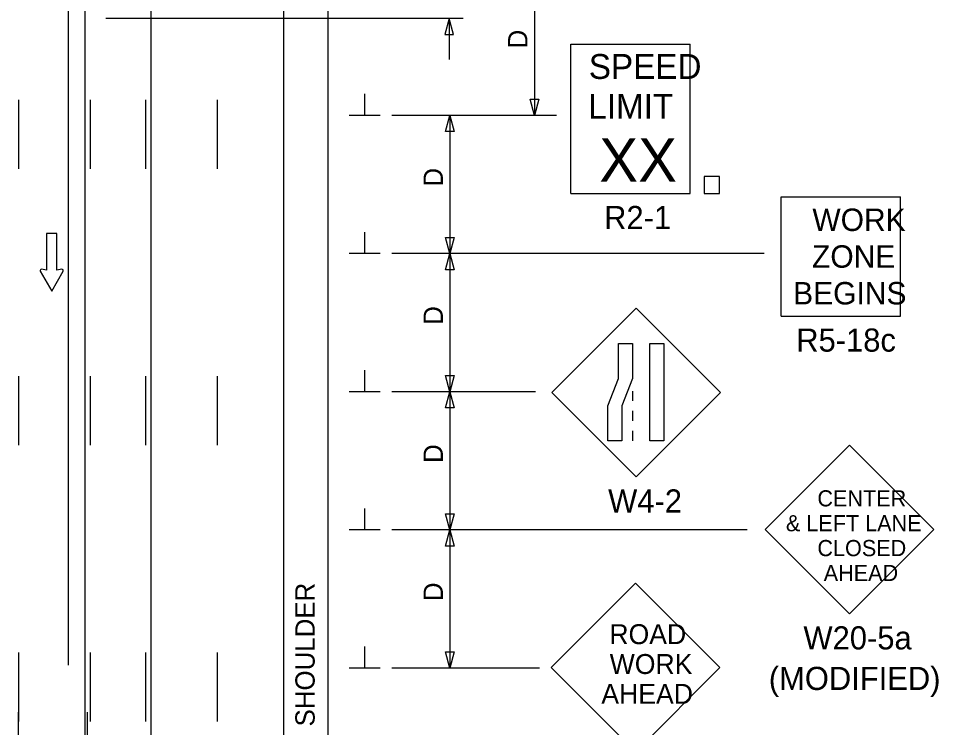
# Model space of a CAD drawing. Extents: x 16735 to 18475, y 6983 to 8262.
# Drawn here: x 17017.1 to 17350.3, y 7410.5 to 7667.2 of the extents above; entities that cross this region are included whole.
import ezdxf

# ---------------------------------------------------------------- set-up
doc = ezdxf.new("R2010")
doc.units = 0
for name, color, linetype in [('ALI_LEGAL_EX', 7, 'Continuous'), ('MT_SCRATCH_LEVEL_E', 7, 'Continuous'), ('PAVT_EDGE_EX', 7, 'Continuous'), ('TRAFFIC_SIGNS_PR', 7, 'Continuous'), ('TYPICAL_TEXT_DIMEN_PR', 7, 'Continuous')]:
    doc.layers.add(name, color=color, linetype=linetype)

msp = doc.modelspace()

# ---------------------------------------------------------------- linework, layer by layer
at = {"layer": 'ALI_LEGAL_EX'}
for points in [[(17017.08, 7637.7), (17017.08, 7612.7)], [(17043.08, 7637.7), (17043.08, 7612.7)], [(17063.08, 7637.7), (17063.08, 7612.7)], [(17089.08, 7637.7), (17089.08, 7612.7)], [(17017.08, 7537.7), (17017.08, 7512.7)], [(17043.08, 7537.7), (17043.08, 7512.7)], [(17063.08, 7537.7), (17063.08, 7512.7)], [(17089.08, 7537.7), (17089.08, 7512.7)], [(17017.08, 7437.7), (17017.08, 7412.7)], [(17043.08, 7437.7), (17043.08, 7412.7)], [(17063.08, 7437.7), (17063.08, 7412.7)], [(17089.08, 7437.7), (17089.08, 7412.7)]]:
    msp.add_lwpolyline(points, dxfattribs=at)
at = {"layer": 'MT_SCRATCH_LEVEL_E'}
for p, q in [((17031.01, 7589.33), (17027.26, 7589.33)), ((17027.26, 7589.33), (17027.26, 7576.07)), ((17031.01, 7589.33), (17027.26, 7589.33)), ((17027.26, 7589.33), (17027.26, 7576.07)), ((17031.01, 7576.07), (17031.01, 7589.33)), ((17031.01, 7576.07), (17031.01, 7589.33)), ((17025.01, 7575.7), (17029.15, 7568.46)), ((17025.01, 7575.7), (17029.15, 7568.46)), ((17027.26, 7576.07), (17025.49, 7576.38)), ((17027.26, 7576.07), (17025.49, 7576.38)), ((17029.15, 7568.46), (17033.27, 7575.7)), ((17029.15, 7568.46), (17033.27, 7575.7)), ((17032.78, 7576.38), (17031.01, 7576.07)), ((17032.78, 7576.38), (17031.01, 7576.07))]:
    msp.add_line(p, q, dxfattribs=at)
for centre, start, end in [((17025.42, 7575.92), 80.0362, 209.7731), ((17025.42, 7575.92), 80.0362, 209.7731), ((17032.86, 7575.92), 330.4248, 99.9638), ((17032.86, 7575.92), 330.4248, 99.9638)]:
    msp.add_arc(centre, 0.463, start, end, dxfattribs=at)
at = {"layer": 'PAVT_EDGE_EX'}
for p, q in [((17035.15, 8262.34), (17035.15, 7433.15)), ((17041.08, 8195.21), (17041.08, 7357.91)), ((17065.08, 8195.21), (17065.08, 7357.91)), ((17113.08, 8195.21), (17113.08, 7357.91)), ((17129.08, 8195.21), (17129.08, 7357.91))]:
    msp.add_line(p, q, dxfattribs=at)
for points in [[(17017.08, 7391.16), (17017.08, 7416.16)], [(17042.08, 7391.16), (17042.08, 7416.16)]]:
    msp.add_lwpolyline(points, dxfattribs=at)
at = {"layer": 'TRAFFIC_SIGNS_PR'}
for p, q in [((17217.14, 7657.79), (17260.34, 7657.79)), ((17217.14, 7603.79), (17217.14, 7657.79)), ((17260.34, 7603.79), (17260.34, 7657.79)), ((17217.14, 7603.79), (17260.34, 7603.79)), ((17293.32, 7559.44), (17293.32, 7602.64)), ((17293.32, 7602.64), (17336.52, 7602.64)), ((17336.52, 7559.44), (17336.52, 7602.64)), ((17240.78, 7562.32), (17210.24, 7531.78)), ((17271.33, 7531.78), (17240.78, 7562.32)), ((17293.32, 7559.44), (17336.52, 7559.44)), ((17210.24, 7531.78), (17240.78, 7501.23)), ((17239.38, 7532.33), (17239.38, 7528.73)), ((17240.78, 7501.23), (17271.33, 7531.78)), ((17239.38, 7525.13), (17239.38, 7521.53)), ((17239.38, 7517.93), (17239.38, 7514.33)), ((17318.05, 7512.78), (17287.51, 7482.23)), ((17348.6, 7482.23), (17318.05, 7512.78)), ((17287.51, 7482.23), (17318.05, 7451.69)), ((17318.05, 7451.69), (17348.6, 7482.23)), ((17240.57, 7462.81), (17210.03, 7432.26)), ((17271.12, 7432.26), (17240.57, 7462.81)), ((17210.03, 7432.26), (17240.57, 7401.72)), ((17240.57, 7401.72), (17271.12, 7432.26))]:
    msp.add_line(p, q, dxfattribs=at)
for points in [[(17265.35, 7603.79), (17270.94, 7603.79), (17270.94, 7609.96), (17265.35, 7609.96)], [(17239.38, 7549.48), (17239.38, 7536.9), (17235.62, 7526.91), (17235.62, 7514.33), (17230.56, 7514.33), (17230.56, 7526.91), (17234.33, 7536.9), (17234.33, 7549.48)], [(17250.78, 7549.48), (17250.78, 7514.33), (17245.73, 7514.33), (17245.73, 7549.48)]]:
    msp.add_lwpolyline(points, close=True, dxfattribs=at)
at = {"layer": 'TYPICAL_TEXT_DIMEN_PR'}
for p, q in [((17203.93, 7682.07), (17203.93, 7632.07)), ((17178.08, 7667.15), (17048.76, 7667.15)), ((17173.08, 7667.15), (17171.51, 7661.29)), ((17173.08, 7667.15), (17173.08, 7652.23)), ((17174.65, 7661.29), (17173.08, 7667.15)), ((17171.51, 7661.29), (17173.08, 7661.29)), ((17173.08, 7661.29), (17174.65, 7661.29)), ((17142.48, 7632.07), (17142.48, 7639.86)), ((17203.93, 7632.07), (17202.36, 7637.93)), ((17202.36, 7637.93), (17203.93, 7637.93)), ((17203.93, 7637.93), (17205.5, 7637.93)), ((17205.5, 7637.93), (17203.93, 7632.07)), ((17148.1, 7632.07), (17136.85, 7632.07)), ((17211.96, 7632.07), (17152.35, 7632.07)), ((17171.78, 7626.21), (17173.35, 7632.07)), ((17173.35, 7632.07), (17174.92, 7626.21)), ((17173.35, 7632.07), (17173.35, 7582.07)), ((17173.35, 7626.21), (17171.78, 7626.21)), ((17174.92, 7626.21), (17173.35, 7626.21)), ((17142.48, 7582.07), (17142.48, 7589.86)), ((17173.35, 7582.07), (17171.78, 7587.93)), ((17171.78, 7587.93), (17173.35, 7587.93)), ((17173.35, 7587.93), (17174.92, 7587.93)), ((17174.92, 7587.93), (17173.35, 7582.07)), ((17148.1, 7582.07), (17136.85, 7582.07)), ((17287.17, 7582.07), (17152.35, 7582.07)), ((17171.78, 7576.21), (17173.35, 7582.07)), ((17173.35, 7582.07), (17174.92, 7576.21)), ((17173.35, 7582.07), (17173.35, 7532.07)), ((17173.35, 7576.21), (17171.78, 7576.21)), ((17174.92, 7576.21), (17173.35, 7576.21)), ((17142.48, 7532.07), (17142.48, 7539.86)), ((17173.35, 7532.07), (17171.78, 7537.93)), ((17171.78, 7537.93), (17173.35, 7537.93)), ((17173.35, 7537.93), (17174.92, 7537.93)), ((17174.92, 7537.93), (17173.35, 7532.07)), ((17148.1, 7532.07), (17136.85, 7532.07)), ((17204.26, 7532.07), (17152.35, 7532.07)), ((17171.78, 7526.21), (17173.35, 7532.07)), ((17173.35, 7532.07), (17174.92, 7526.21)), ((17173.35, 7532.07), (17173.35, 7482.07)), ((17173.35, 7526.21), (17171.78, 7526.21)), ((17174.92, 7526.21), (17173.35, 7526.21)), ((17142.48, 7482.07), (17142.48, 7489.86)), ((17173.35, 7482.07), (17171.78, 7487.93)), ((17171.78, 7487.93), (17173.35, 7487.93)), ((17173.35, 7487.93), (17174.92, 7487.93)), ((17174.92, 7487.93), (17173.35, 7482.07)), ((17148.1, 7482.07), (17136.85, 7482.07)), ((17280.93, 7482.07), (17152.35, 7482.07)), ((17171.78, 7476.21), (17173.35, 7482.07)), ((17173.35, 7482.07), (17174.92, 7476.21)), ((17173.35, 7482.07), (17173.35, 7432.07)), ((17173.35, 7476.21), (17171.78, 7476.21)), ((17174.92, 7476.21), (17173.35, 7476.21)), ((17142.48, 7432.07), (17142.48, 7439.86)), ((17173.35, 7432.07), (17171.78, 7437.93)), ((17171.78, 7437.93), (17173.35, 7437.93)), ((17173.35, 7437.93), (17174.92, 7437.93)), ((17174.92, 7437.93), (17173.35, 7432.07)), ((17148.1, 7432.07), (17136.85, 7432.07)), ((17205.8, 7432.07), (17152.35, 7432.07))]:
    msp.add_line(p, q, dxfattribs=at)

# ---------------------------------------------------------------- texts
at = {"layer": 'TRAFFIC_SIGNS_PR'}
for s, height, p in [('SPEED', 9, (17223.62, 7645.26)), ('LIMIT', 9, (17223.44, 7630.86)), ('XX', 15.785, (17227.39, 7608.02)), ('R2-1', 8.37, (17229.15, 7590.92)), ('WORK', 8.119, (17304.57, 7590.23)), ('ZONE', 8.119, (17304.44, 7576.94)), ('BEGINS', 8.119, (17297.6, 7563.65)), ('R5-18c', 8.37, (17298.73, 7546.57)), ('W4-2', 8.37, (17230.61, 7488.36)), ('CENTER', 5.85, (17306.39, 7490.57)), ('& LEFT LANE', 5.85, (17294.99, 7481.57)), ('CLOSED', 5.85, (17306.39, 7472.57)), ('AHEAD', 5.85, (17308.67, 7463.57)), ('ROAD', 7.2, (17231.06, 7440.74)), ('W20-5a', 8.37, (17301.33, 7438.82)), ('WORK', 7.2, (17231.18, 7429.94)), ('(MODIFIED)', 8.37, (17288.79, 7424.15)), ('AHEAD', 7.2, (17228.15, 7419.14))]:
    msp.add_text(s, height=height, dxfattribs=at).set_placement(p)
at = {"layer": 'TYPICAL_TEXT_DIMEN_PR'}
for s, p in [('D', (17201.37, 7656.29)), ('D', (17170.79, 7606.29)), ('D', (17170.79, 7556.29)), ('D', (17170.79, 7506.29)), ('SHOULDER', (17124.36, 7410.94)), ('D', (17170.79, 7456.29))]:
    msp.add_text(s, height=7, rotation=90, dxfattribs=at).set_placement(p)

doc.saveas('drawing.dxf')
